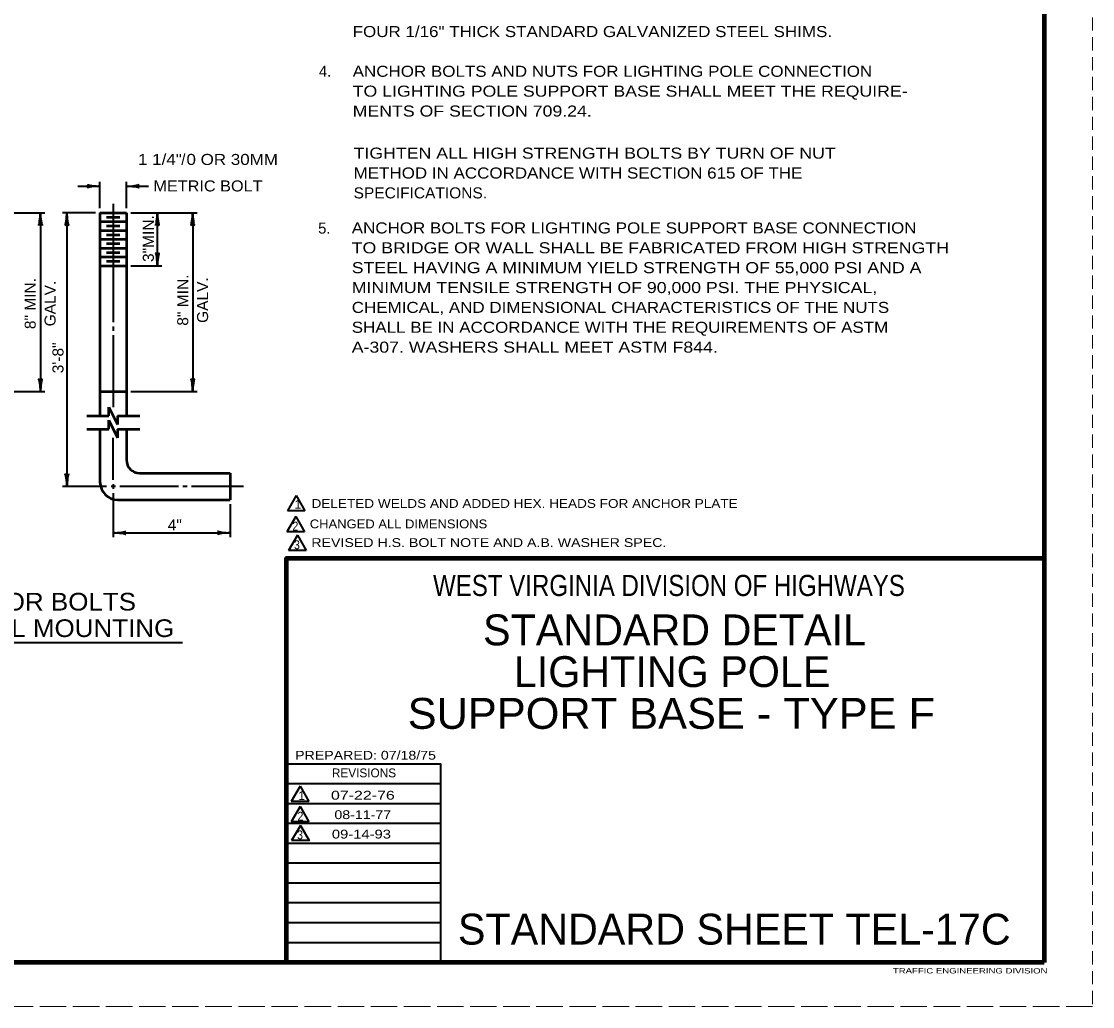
# Model space of a CAD drawing. Extents: x -1 to 679, y 0 to 440.
# Drawn here: x 436 to 678.6, y -0.4 to 222.7 of the extents above; entities that cross this region are included whole.
import ezdxf
from ezdxf.enums import TextEntityAlignment as Align

# ---------------------------------------------------------------- set-up
doc = ezdxf.new("R2010")
doc.units = 0
doc.linetypes.add('LONG_DASHED', pattern=[7.5, 6, -1.5])
doc.linetypes.add('MEDIUM_DASHED', pattern=[4.5, 3, -1.5])
doc.layers.add('1', color=7, linetype='Continuous', lineweight=53)
doc.layers.add('61', color=7, linetype='Continuous', lineweight=35)

msp = doc.modelspace()

# ---------------------------------------------------------------- linework, layer by layer
at = {"layer": '1', "linetype": 'MEDIUM_DASHED', "lineweight": 13}
msp.add_line((678.644, 439.629), (678.624, -0.391), dxfattribs=at)
at = {"layer": '1', "lineweight": 35}
for p, q in [((448.77, 185.378), (453.77, 185.378)), ((453.77, 180.378), (453.77, 186.378)), ((459.77, 180.378), (459.77, 186.378)), ((459.77, 185.378), (464.77, 185.378)), ((456.77, 181.378), (456.77, 154.628)), ((429.27, 179.378), (441.27, 179.378)), ((440.27, 179.378), (440.27, 138.878)), ((452.77, 179.378), (445.27, 179.378)), ((446.27, 179.378), (446.27, 117.378)), ((460.77, 179.378), (475.77, 179.378)), ((466.77, 167.378), (466.77, 179.378)), ((474.77, 179.378), (474.77, 138.878)), ((460.77, 167.378), (467.77, 167.378)), ((456.77, 153.628), (456.77, 152.628)), ((456.77, 151.628), (456.77, 135.378)), ((429.27, 138.878), (441.27, 138.878)), ((460.77, 138.878), (475.77, 138.878)), ((456.77, 118.878), (456.77, 128.378)), ((455.27, 117.378), (445.27, 117.378)), ((457.27, 117.378), (456.27, 117.378)), ((456.77, 117.878), (456.77, 116.878)), ((471.52, 117.378), (458.27, 117.378)), ((473.52, 117.378), (472.52, 117.378)), ((486.27, 117.378), (474.52, 117.378)), ((456.77, 115.878), (456.77, 105.878)), ((498.213, 115.36), (496.213, 111.896)), ((498.213, 115.36), (500.213, 111.896)), ((483.27, 113.378), (483.27, 105.878)), ((500.213, 111.896), (496.213, 111.896)), ((498.128, 110.559), (496.128, 107.095)), ((498.128, 110.559), (500.128, 107.095)), ((456.77, 106.878), (483.27, 106.878)), ((500.128, 107.095), (496.128, 107.095)), ((498.48, 106.328), (496.48, 102.863)), ((498.48, 106.328), (500.48, 102.863)), ((500.48, 102.863), (496.48, 102.863)), ((404.637, 82.006), (472.426, 82.006)), ((531.024, 50.029), (496.044, 50.029)), ((499.098, 49.472), (497.098, 46.008)), ((499.098, 49.472), (501.098, 46.008)), ((531.024, 45.529), (496.044, 45.529)), ((499.093, 44.888), (497.093, 41.424)), ((501.098, 46.008), (497.098, 46.008)), ((499.093, 44.888), (501.093, 41.424)), ((501.093, 41.424), (497.093, 41.424)), ((531.024, 41.029), (496.044, 41.029)), ((499.181, 40.628), (497.181, 37.164)), ((531.024, 36.509), (496.044, 36.509)), ((531.024, 32.029), (496.044, 32.029)), ((531.024, 27.549), (496.044, 27.549)), ((531.024, 23.049), (496.044, 23.049)), ((531.024, 18.549), (496.044, 18.549)), ((531.024, 14.029), (496.044, 14.029))]:
    msp.add_line(p, q, dxfattribs=at)
at = {"layer": '1'}
for p, q in [((453.77, 179.378), (459.77, 179.378)), ((453.77, 179.378), (453.77, 133.378)), ((453.77, 177.378), (459.77, 177.378)), ((455.27, 178.378), (458.27, 178.378)), ((459.77, 179.378), (459.77, 133.378)), ((453.77, 175.378), (459.77, 175.378)), ((455.27, 176.378), (458.27, 176.378)), ((453.77, 173.378), (459.77, 173.378)), ((455.27, 174.378), (458.27, 174.378)), ((455.27, 172.378), (458.27, 172.378)), ((453.77, 171.378), (459.77, 171.378)), ((455.27, 170.378), (458.27, 170.378)), ((453.77, 169.378), (459.77, 169.378)), ((455.27, 168.378), (458.27, 168.378)), ((453.77, 167.378), (459.77, 167.378)), ((453.77, 138.878), (459.77, 138.878)), ((455.77, 133.378), (455.77, 135.378)), ((455.77, 135.378), (457.77, 131.378)), ((450.77, 133.378), (455.77, 133.378)), ((455.77, 130.378), (455.77, 132.378)), ((455.77, 132.378), (457.77, 128.378)), ((457.77, 133.378), (462.77, 133.378)), ((457.77, 133.378), (457.77, 131.378)), ((450.77, 130.378), (455.77, 130.378)), ((453.77, 130.378), (453.77, 118.378)), ((457.77, 130.378), (462.77, 130.378)), ((457.77, 130.378), (457.77, 128.378)), ((459.77, 130.378), (459.77, 123.378)), ((462.77, 120.378), (483.27, 120.378)), ((483.27, 120.378), (483.27, 114.378)), ((457.77, 114.378), (483.27, 114.378))]:
    msp.add_line(p, q, dxfattribs=at)
at = {"layer": '1', "lineweight": 158}
msp.add_lwpolyline([(496.024, 9.589), (496.024, 101.169), (667.684, 101.169)], dxfattribs=at)
at = {"layer": '1', "lineweight": 35}
for points in [[(531.024, 9.549), (531.024, 54.509), (496.044, 54.509)], [(499.181, 40.628), (501.181, 37.164), (497.181, 37.164)]]:
    msp.add_lwpolyline(points, dxfattribs=at)
at = {"layer": '1'}
for centre, radius in [((462.77, 123.378), 3), ((457.77, 118.378), 4)]:
    msp.add_arc(centre, radius, 180, 270, dxfattribs=at)
at = {"layer": '1', "lineweight": 40}
for centre, major_axis, ratio, start_param, end_param in [((452.679, 185.101), (1.786, 0.156), 0.122415, 0.8963533, 3.1415927), ((452.65, 185.589), (1.756, -0.176), 0.07063, 3.1407148, 5.41811), ((460.891, 185.166), (-1.756, 0.176), 0.07063, 3.1407148, 5.41811), ((460.862, 185.654), (-1.786, -0.156), 0.122415, 0.8963533, 3.1415927), ((440.059, 178.257), (0.176, 1.756), 0.07063, 3.1407148, 5.41811), ((440.059, 178.257), (0.176, 1.756), 0.07063, 3.1407148, 5.41811), ((440.547, 178.287), (-0.156, 1.786), 0.122415, 0.8963533, 3.1415927), ((440.547, 178.287), (-0.156, 1.786), 0.122415, 0.8963533, 3.1415927), ((446.059, 178.257), (0.176, 1.756), 0.07063, 3.1407148, 5.41811), ((446.059, 178.257), (0.176, 1.756), 0.07063, 3.1407148, 5.41811), ((446.547, 178.287), (-0.156, 1.786), 0.122415, 0.8963533, 3.1415927), ((446.547, 178.287), (-0.156, 1.786), 0.122415, 0.8963533, 3.1415927), ((466.559, 178.257), (0.176, 1.756), 0.07063, 3.1407148, 5.41811), ((466.559, 178.257), (0.176, 1.756), 0.07063, 3.1407148, 5.41811), ((467.047, 178.287), (-0.156, 1.786), 0.122415, 0.8963533, 3.1415927), ((467.047, 178.287), (-0.156, 1.786), 0.122415, 0.8963533, 3.1415927), ((474.559, 178.257), (0.176, 1.756), 0.07063, 3.1407148, 5.41811), ((474.559, 178.257), (0.176, 1.756), 0.07063, 3.1407148, 5.41811), ((475.047, 178.287), (-0.156, 1.786), 0.122415, 0.8963533, 3.1415927), ((475.047, 178.287), (-0.156, 1.786), 0.122415, 0.8963533, 3.1415927), ((466.494, 168.469), (0.156, -1.786), 0.122415, 0.8963533, 3.1415927), ((466.494, 168.469), (0.156, -1.786), 0.122415, 0.8963533, 3.1415927), ((466.982, 168.498), (-0.176, -1.756), 0.07063, 3.1407148, 5.41811), ((466.982, 168.498), (-0.176, -1.756), 0.07063, 3.1407148, 5.41811), ((439.994, 139.969), (0.156, -1.786), 0.122415, 0.8963533, 3.1415927), ((439.994, 139.969), (0.156, -1.786), 0.122415, 0.8963533, 3.1415927), ((440.482, 139.998), (-0.176, -1.756), 0.07063, 3.1407148, 5.41811), ((440.482, 139.998), (-0.176, -1.756), 0.07063, 3.1407148, 5.41811), ((474.494, 139.969), (0.156, -1.786), 0.122415, 0.8963533, 3.1415927), ((474.494, 139.969), (0.156, -1.786), 0.122415, 0.8963533, 3.1415927), ((474.982, 139.998), (-0.176, -1.756), 0.07063, 3.1407148, 5.41811), ((474.982, 139.998), (-0.176, -1.756), 0.07063, 3.1407148, 5.41811), ((445.994, 118.469), (0.156, -1.786), 0.122415, 0.8963533, 3.1415927), ((445.994, 118.469), (0.156, -1.786), 0.122415, 0.8963533, 3.1415927), ((446.482, 118.498), (-0.176, -1.756), 0.07063, 3.1407148, 5.41811), ((446.482, 118.498), (-0.176, -1.756), 0.07063, 3.1407148, 5.41811), ((457.891, 106.666), (-1.756, 0.176), 0.07063, 3.1407148, 5.41811), ((457.891, 106.666), (-1.756, 0.176), 0.07063, 3.1407148, 5.41811), ((457.862, 107.154), (-1.786, -0.156), 0.122415, 0.8963533, 3.1415927), ((457.862, 107.154), (-1.786, -0.156), 0.122415, 0.8963533, 3.1415927), ((482.179, 106.601), (1.786, 0.156), 0.122415, 0.8963533, 3.1415927), ((482.179, 106.601), (1.786, 0.156), 0.122415, 0.8963533, 3.1415927), ((482.15, 107.089), (1.756, -0.176), 0.07063, 3.1407148, 5.41811), ((482.15, 107.089), (1.756, -0.176), 0.07063, 3.1407148, 5.41811)]:
    msp.add_ellipse(centre, major_axis=major_axis, ratio=ratio, start_param=start_param, end_param=end_param, dxfattribs=at)
at = {"layer": '61', "lineweight": 158}
for p, q in [((667.664, 429.629), (667.684, 9.589)), ((667.684, 9.589), (28.624, 9.609))]:
    msp.add_line(p, q, dxfattribs=at)
at = {"layer": '61', "linetype": 'LONG_DASHED', "lineweight": 13}
msp.add_line((678.624, -0.391), (-1.436, -0.411), dxfattribs=at)

# ---------------------------------------------------------------- texts
at = {"layer": '1'}
for s, height, width, p in [('FOUR 1/16" THICK STANDARD GALVANIZED STEEL SHIMS.', 2.5, 1.15, (511.018, 219.159)), ('ANCHOR BOLTS AND NUTS FOR LIGHTING POLE CONNECTION', 2.5, 1.15, (511.018, 210.159)), ('TO LIGHTING POLE SUPPORT BASE SHALL MEET THE REQUIRE-', 2.5, 1.2, (511.018, 205.659)), ('MENTS OF SECTION 709.24.', 2.5, 1.2, (511.018, 201.159)), ('TIGHTEN ALL HIGH STRENGTH BOLTS BY TURN OF NUT', 2.5, 1.2, (511.231, 191.621)), ('METHOD IN ACCORDANCE WITH SECTION 615 OF THE', 2.5, 1.15, (511.231, 187.121)), ('SPECIFICATIONS.', 2.5, 1.05, (511.231, 182.621)), ('ANCHOR BOLTS FOR LIGHTING POLE SUPPORT BASE CONNECTION', 2.5, 1.15, (510.805, 174.683)), ('TO BRIDGE OR WALL SHALL BE FABRICATED FROM HIGH STRENGTH', 2.5, 1.2, (510.805, 170.183)), ('STEEL HAVING A MINIMUM YIELD STRENGTH OF 55,000 PSI AND A', 2.5, 1.2, (510.805, 165.683)), ('MINIMUM TENSILE STRENGTH OF 90,000 PSI. THE PHYSICAL,', 2.5, 1.2, (510.805, 161.183)), ('CHEMICAL, AND DIMENSIONAL CHARACTERISTICS OF THE NUTS', 2.5, 1.15, (510.805, 156.683)), ('SHALL BE IN ACCORDANCE WITH THE REQUIREMENTS OF ASTM', 2.5, 1.15, (510.805, 152.183)), ('A-307. WASHERS SHALL MEET ASTM F844.', 2.5, 1.2, (510.805, 147.683)), ('DELETED WELDS AND ADDED HEX. HEADS FOR ANCHOR PLATE', 2, 1.15, (501.693, 112.527)), ('2', 2, 0.9, (497.363, 107.408)), ('CHANGED ALL DIMENSIONS', 2, 1.1, (501.3, 107.901)), ('3', 2, 0.9, (497.716, 103.177)), ('REVISED H.S. BOLT NOTE AND A.B. WASHER SPEC.', 2, 1.2, (501.652, 103.669)), ('PREPARED: 07/18/75', 1.998, 1.2, (497.984, 55.509)), ('2', 2, 0.9, (498.51, 41.692)), ('3', 2, 0.9, (498.416, 37.477)), ('TRAFFIC ENGINEERING DIVISION', 1.2, 1.35, (633.404, 7.089))]:
    msp.add_text(s, height=height, dxfattribs=dict(at, width=width)).set_placement(p)
for s, height, p in [('4.', 2.5, (504.765, 210.161)), ('/', 2.5, (472.66, 190.209)), ('5.', 2.5, (504.595, 174.643)), ('STANDARD DETAIL', 6.993, (583.941, 81.409)), ('LIGHTING POLE', 6.993, (583.387, 71.951))]:
    msp.add_text(s, height=height, dxfattribs=at).set_placement(p, align=Align.CENTER)
for s, height, width, p in [('1 1/4" 0 OR 30MM', 2.5, 1.15, (478.236, 190.194)), ('METRIC BOLT', 2.5, 1.1, (478.236, 184.194)), ('4"', 2.5, 1.05, (470.716, 107.426)), ('WEST VIRGINIA DIVISION OF HIGHWAYS', 4.795, 0.85, (582.672, 92.569)), ('ANCHOR BOLTS', 4, 1.1, (438.728, 89.283)), ('FOR WALL MOUNTING', 4, 1.1, (438.728, 83.283)), ('SUPPORT BASE - TYPE F', 6.993, 1.05, (583.218, 62.493)), ('07-22-76', 2, 1.35, (513.324, 46.449)), ('08-11-77', 2, 1.2, (513.304, 42.049)), ('09-14-93', 2, 1.25, (512.993, 37.649))]:
    msp.add_text(s, height=height, dxfattribs=dict(at, width=width)).set_placement(p, align=Align.CENTER)
at = {"layer": '1', "width": 1.05}
for s, p in [('3"MIN.', (465.974, 173.523)), ('8" MIN.', (473.765, 159.585)), ('8" MIN.', (439.206, 158.807)), ('GALV.', (443.706, 158.807)), ('GALV.', (478.265, 159.586)), ('3\'-8"', (445.503, 146.505))]:
    msp.add_text(s, height=2.5, rotation=90, dxfattribs=at).set_placement(p, align=Align.CENTER)
at = {"layer": '1'}
for s, height, p in [('1', 2, (497.855, 112.331)), ('REVISIONS', 1.998, (506.304, 51.509)), ('1', 2, (498.702, 46.354)), ('STANDARD SHEET TEL-17C', 6.993, (534.864, 13.629))]:
    msp.add_text(s, height=height, dxfattribs=at).set_placement(p)

doc.saveas('drawing.dxf')
